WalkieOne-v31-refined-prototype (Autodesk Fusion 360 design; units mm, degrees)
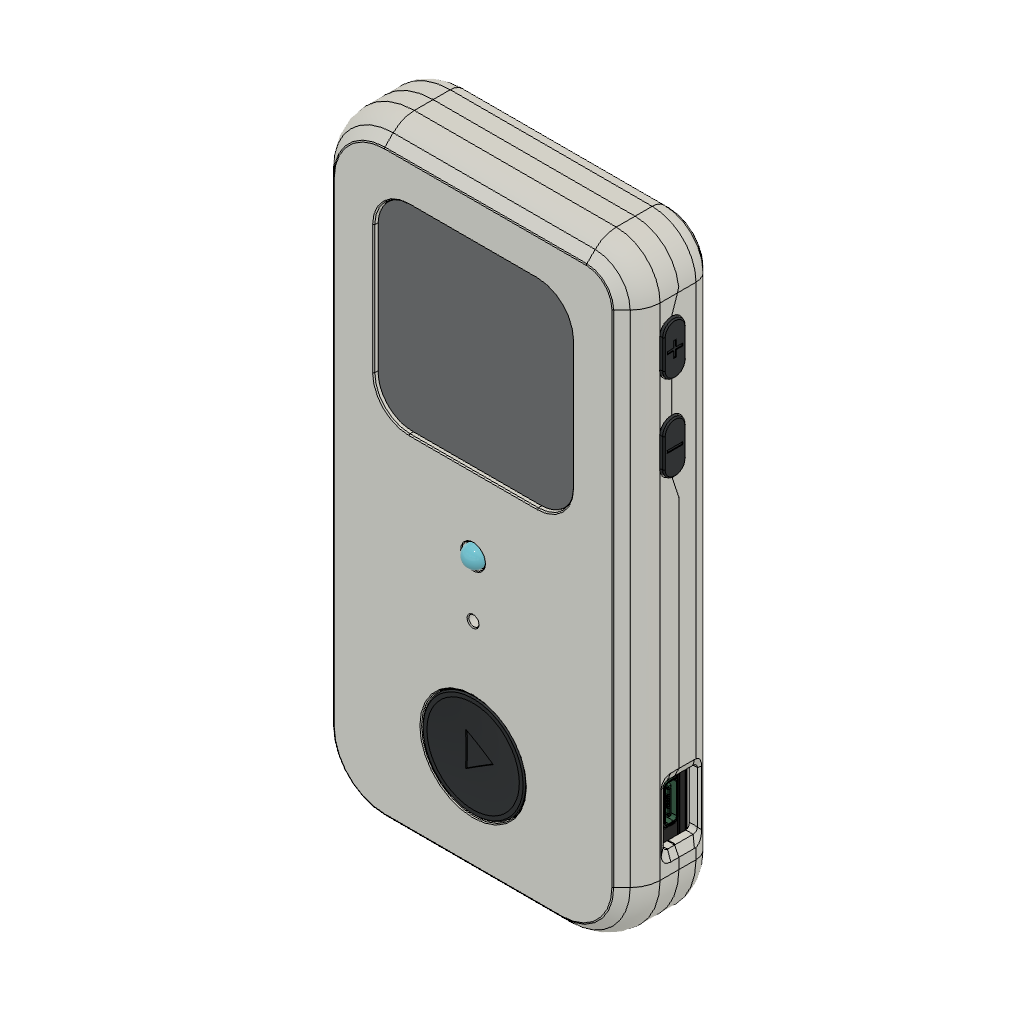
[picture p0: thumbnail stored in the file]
description: Part Number
part number: WO-V31-ASM
part number: WO-V31-M01
part number: WO-V31-M02
part number: WO-V31-M03
part number: WO-V31-M04
part number: WO-V31-M05
part number: WO-V31-M06
part number: WO-V31-M07
part number: WO-V31-M08
part number: WO-V31-M09
part number: WO-V31-M99
part number: WO-V31-BACK
part number: WO-V31-BATTERY_REFERENCE
part number: WO-V31-CASE_INSERTS_REFERENCE
part number: WO-V31-CASE_SCREWS_REFERENCE
parameter "REF_Body_Width" = 73.5 comment "Preserved v30 envelope; reference only, does not resize imported shells."
parameter "REF_Body_Height" = 143.25 comment "Preserved v30 envelope; reference only."
parameter "REF_Body_Thickness" = 19.4 comment "Preserved v30 envelope; excludes existing projections."
parameter "PTT_Link_Centres" = 8 comment "Link pivot centre spacing."
parameter "PTT_Link_Width" = 6.8 comment "Link capsule width."
parameter "PTT_Link_Bore" = 4.1 comment "Bearing bore; 0.1 mm diametral clearance over sleeve."
parameter "PTT_Link_Thickness" = 2.4 comment "Link thickness."
parameter "PTT_Sleeve_Flange_OD" = 6.6 comment "Sleeve flange diameter."
parameter "PTT_Sleeve_Bearing_OD" = 4 comment "Link bearing diameter."
parameter "PTT_Sleeve_Bore" = 2.3 comment "Screw clearance diameter."
parameter "PTT_Sleeve_Flange_T" = 1.2 comment "Sleeve flange thickness."
parameter "PTT_Sleeve_Bearing_L" = 2.55 comment "Bearing length; retains 0.15 mm total axial clearance."
parameter "Speaker_Spacer_OD" = 5 comment "Printed spacer diameter."
parameter "Speaker_Spacer_ID" = 2.2 comment "Speaker spacer clearance bore."
parameter "Speaker_Spacer_T" = 0.7 comment "Accepted v30 speaker stack thickness."
base_feature "Base Feature1" bodies "Rear shell"
base_feature "Base Feature1" bodies "Battery"
base_feature "Base Feature1" bodies "Case inserts 001", "Case inserts 002", "Case inserts 003", "Case inserts 004", "Battery"
base_feature "Base Feature1" bodies "Case screws 001", "Case screws 002", "Case screws 003", "Case screws 004", "Battery"
base_feature "Base Feature1" bodies "Front shell"
base_feature "Base Feature1" bodies "Grille adhesive - 0.26 mm"
base_feature "Base Feature1" bodies "Metal grille blank - 46 x 46 R8"
base_feature "Base Feature1" bodies "LED body"
base_feature "Base Feature1" bodies "LED formed leads 001", "LED formed leads 002", "LED formed leads 003", "LED formed leads 004"
base_feature "Base Feature1" bodies "LED inserts 001", "LED inserts 002"
base_feature "Base Feature1" bodies "LED insulated joint keepout 001", "LED insulated joint keepout 002", "LED insulated joint keepout 003", "LED insulated joint keepout 004", "Battery"
base_feature "Base Feature1" bodies "LED fork retainer"
base_feature "Base Feature1" bodies "LED screws 001", "LED screws 002"
base_feature "Base Feature1" bodies "LED soft pad"
base_feature "Base Feature1" bodies "Microphone gasket"
base_feature "Base Feature1" bodies "Microphone inserts 001", "Microphone inserts 002"
base_feature "Base Feature1" bodies "Microphone 001", "Microphone 002", "Microphone 003", "Microphone 004", "Microphone 005", "Microphone 006"
base_feature "Base Feature1" bodies "Microphone screws 001", "Microphone screws 002"
base_feature "Base Feature1" bodies "Microphone wire keepout"
base_feature "Base Feature1" bodies "PCB - exact fit reference 001", "PCB - exact fit reference 002", "PCB - exact fit reference 003", "PCB - exact fit reference 004", "PCB - exact fit reference 005", "PCB - exact fit reference 006", "PCB - exact fit reference 007", "PCB - exact fit reference 008"
base_feature "Base Feature1" bodies "PTT button cap"
base_feature "Base Feature1" bodies "PTT fixed screw 0"
base_feature "Base Feature1" bodies "PTT fixed screw 1"
base_feature "Base Feature1" bodies "PTT inserts 001", "PTT inserts 002", "PTT inserts 003", "PTT inserts 004", "PTT inserts 005", "PTT inserts 006"
base_feature "Base Feature1" bodies "PTT lower wire"
base_feature "Base Feature1" bodies "PTT mount screw 0"
base_feature "Base Feature1" bodies "PTT mount screw 1"
base_feature "Base Feature1" bodies "PTT moving screw 0"
base_feature "Base Feature1" bodies "PTT moving screw 1"
base_feature "Base Feature1" bodies "PTT switch"
base_feature "Base Feature1" bodies "PTT switch clamp"
base_feature "Base Feature1" bodies "PTT switch seat"
base_feature "Base Feature1" bodies "PTT upper wire"
base_feature "Base Feature1" bodies "Play button cap"
base_feature "Base Feature1" bodies "Play switch carrier"
base_feature "Base Feature1" bodies "Play foam 001", "Play foam 002", "Play foam 003", "Play foam 004", "Battery"
base_feature "Base Feature1" bodies "Play inserts 001", "Play inserts 002"
base_feature "Base Feature1" bodies "Play travel retainer - C 0.40"
base_feature "Base Feature1" bodies "Play screws 001", "Play screws 002"
base_feature "Base Feature1" bodies "Play switch"
base_feature "Base Feature1" bodies "Play wire keepout 001", "Play wire keepout 002", "Play wire keepout 003", "Play wire keepout 004", "Battery"
base_feature "Base Feature1" bodies "Speaker gasket"
base_feature "Base Feature1" bodies "Speaker inserts 001", "Speaker inserts 002"
base_feature "Base Feature1" bodies "Speaker 001", "Speaker 002", "Speaker 003", "Speaker 004", "Battery"
base_feature "Base Feature1" bodies "Speaker screws 001", "Speaker screws 002"
base_feature "Base Feature1" bodies "Speaker washers 001", "Speaker washers 002"
base_feature "Base Feature1" bodies "USB collar"
base_feature "Base Feature1" bodies "USB liner backers 001", "USB liner backers 002"
base_feature "Base Feature1" bodies "USB liner floor lift"
base_feature "Base Feature1" bodies "USB liner floor sides 001", "USB liner floor sides 002"
base_feature "Base Feature1" bodies "USB liner inner returns"
base_feature "Base Feature1" bodies "USB liner primary 001", "USB liner primary 002", "USB liner primary 003", "USB liner primary 004", "USB liner primary 005", "USB liner primary 006", "USB liner primary 007", "USB liner primary 008"
base_feature "Base Feature1" bodies "Volume body adhesive 001", "Volume body adhesive 002"
base_feature "Base Feature1" bodies "Volume minus cap"
base_feature "Base Feature1" bodies "Volume down switch"
base_feature "Base Feature1" bodies "Volume down wire A 001", "Volume down wire A 002", "Volume down wire A 003", "Volume down wire A 004", "Volume down wire A 005", "Volume down wire A 006", "Volume down wire A 007", "Volume down wire A 008"
base_feature "Base Feature1" bodies "Volume down wire B 001", "Volume down wire B 002", "Volume down wire B 003", "Volume down wire B 004", "Volume down wire B 005", "Volume down wire B 006", "Volume down wire B 007", "Volume down wire B 008"
base_feature "Base Feature1" bodies "Volume guide frame"
base_feature "Base Feature1" bodies "Volume insert 130"
base_feature "Base Feature1" bodies "Volume insert 93"
base_feature "Base Feature1" bodies "Volume switch keeper"
base_feature "Base Feature1" bodies "Volume screw 130"
base_feature "Base Feature1" bodies "Volume screw 93"
base_feature "Base Feature1" bodies "Volume plus cap"
base_feature "Base Feature1" bodies "Volume up switch"
base_feature "Base Feature1" bodies "Volume up wire A 001", "Volume up wire A 002", "Volume up wire A 003", "Volume up wire A 004", "Volume up wire A 005", "Volume up wire A 006", "Volume up wire A 007", "Volume up wire A 008"
base_feature "Base Feature1" bodies "Volume up wire B 001", "Volume up wire B 002", "Volume up wire B 003", "Volume up wire B 004", "Volume up wire B 005", "Volume up wire B 006", "Volume up wire B 007", "Volume up wire B 008"
place_component sketch "Link capsule and bearing bores"
sketch "Link capsule and bearing bores" plane through (0, 0, 0) normal (0, 0, 1) x axis (1, 0, 0)
  line L1 (8, -3.4) -> (0, -3.4)
  line L2 (0, 3.4) -> (8, 3.4)
  line L3 (8, 0) -> (0, 0)
  arc A1 centre (8, 0) radius 3.4 clockwise from (8, 3.4) to (8, -3.4)
  arc A2 centre (0, 0) radius 3.4 clockwise from (0, -3.4) to (0, 3.4)
  circle C1 centre (0, 0) radius 2.05
  circle C2 centre (8, 0) radius 2.05
  point P1 (0, 0)
  point P6 (0, 0)
  point P8 (0, 0)
  point P7 (8, 0)
  point P9 (8, 0)
  coincident P1 P6
  tangent L1 A1
  tangent A1 L2
  tangent L2 A2
  tangent L1 A2
  parallel L1 L2
  horizontal L3
  coincident P6 P8
  coincident P7 P9
  dimension "d16" diameter A1 = 6.8
  dimension "d17" distance P6 P7 = 8
  dimension "d18" diameter C1 = 4.1 (= "PTT_Link_Bore")
  dimension "d19" diameter C2 = 4.1 (= "PTT_Link_Bore")
extrude "Extrude1" new body sketch "Link capsule and bearing bores" profile of L1 A1 L2 A2 C1 C2 along normal blind 2.4 (= "PTT_Link_Thickness") bodies "PTT link - 8 mm centres"
copy_paste "CopyPaste1"
sketch "Flange and M2 clearance bore" plane through (0, 0, 0) normal (0, 0, 1) x axis (1, 0, 0)
  circle C1 centre (0, 0) radius 3.3
  circle C2 centre (0, 0) radius 1.15
  point P1 (0, 0)
  point P2 (0, 0)
  point P3 (0, 0)
  coincident P1 P2
  coincident P1 P3
  dimension "d22" diameter C1 = 6.6 (= "PTT_Sleeve_Flange_OD")
  dimension "d23" diameter C2 = 2.3 (= "PTT_Sleeve_Bore")
extrude "Extrude1" new body sketch "Flange and M2 clearance bore" along normal blind 1.2 (= "PTT_Sleeve_Flange_T") bodies "PTT shoulder sleeve - 4 places"
work_plane "WorkPlane1" AlongDistance 1.2 (= "PTT_Sleeve_Flange_T") ExtraOffset 0
sketch "Bearing diameter and clearance bore" plane through (0, 0, 1.2) normal (0, 0, 1) x axis (1, 0, 0)
  circle C1 centre (0, 0) radius 2
  circle C2 centre (0, 0) radius 1.15
  point P1 (0, 0)
  point P2 (0, 0)
  point P3 (0, 0)
  coincident P1 P2
  coincident P1 P3
  dimension "d28" diameter C1 = 4 (= "PTT_Sleeve_Bearing_OD")
  dimension "d29" diameter C2 = 2.3 (= "PTT_Sleeve_Bore")
extrude "Extrude2" add sketch "Bearing diameter and clearance bore" along normal blind 2.55 (= "PTT_Sleeve_Bearing_L")
copy_paste "CopyPaste2"
copy_paste "CopyPaste3"
copy_paste "CopyPaste4"
place_component sketch "Speaker spacer annulus"
sketch "Speaker spacer annulus" plane through (0, 0, 0) normal (0, 0, 1) x axis (1, 0, 0)
  circle C1 centre (0, 0) radius 2.5
  circle C2 centre (0, 0) radius 1.1
  point P1 (0, 0)
  point P2 (0, 0)
  point P3 (0, 0)
  coincident P1 P2
  coincident P1 P3
  dimension "d32" diameter C1 = 5 (= "Speaker_Spacer_OD")
  dimension "d33" diameter C2 = 2.2 (= "Speaker_Spacer_ID")
extrude "Extrude1" new body sketch "Speaker spacer annulus" along normal blind 0.7 (= "Speaker_Spacer_T") bodies "Speaker spacer - 0.7 mm - 2 places"
copy_paste "CopyPaste1"
position "Position1"
sketch "REFERENCE ONLY - preserved v30 73.5 x 143.25 envelope" plane through (0, 0, 0) normal (0, 0, 1) x axis (1, 0, 0)
  line L1 (72.75, -0.75) -> (-0.75, -0.75)
  line L2 (72.75, 142.5) -> (72.75, -0.75)
  line L3 (-0.75, 142.5) -> (72.75, 142.5)
  line L4 (-0.75, -0.75) -> (-0.75, 142.5)
position "Position2"
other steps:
create_component "CreateComponent1"
create_component "CreateComponent2"
create_component "CreateComponent3"
create_component "CreateComponent4"
create_component "CreateComponent5"
create_component "CreateComponent6"
create_component "CreateComponent7"
create_component "CreateComponent8"
create_component "CreateComponent9"
create_component "CreateComponent10"
create_component "CreateComponent1"
create_component "CreateComponent1"
create_component "CreateComponent1"
create_component "CreateComponent2"
create_component "CreateComponent2"
create_component "CreateComponent1"
create_component "CreateComponent2"
create_component "CreateComponent1"
create_component "CreateComponent1"
create_component "CreateComponent2"
create_component "CreateComponent2"
create_component "CreateComponent3"
create_component "CreateComponent4"
create_component "CreateComponent5"
create_component "CreateComponent2"
create_component "CreateComponent3"
create_component "CreateComponent4"
create_component "CreateComponent5"
create_component "CreateComponent3"
create_component "CreateComponent6"
create_component "CreateComponent1"
create_component "CreateComponent2"
create_component "CreateComponent3"
create_component "CreateComponent4"
create_component "CreateComponent4"
create_component "CreateComponent5"
create_component "CreateComponent6"
create_component "CreateComponent7"
create_component "CreateComponent8"
create_component "CreateComponent9"
create_component "CreateComponent10"
create_component "CreateComponent11"
create_component "CreateComponent5"
create_component "CreateComponent1"
create_component "CreateComponent2"
create_component "CreateComponent3"
create_component "CreateComponent4"
create_component "CreateComponent5"
create_component "CreateComponent6"
create_component "CreateComponent7"
create_component "CreateComponent6"
create_component "CreateComponent3"
create_component "CreateComponent4"
create_component "CreateComponent5"
create_component "CreateComponent6"
create_component "CreateComponent7"
create_component "CreateComponent1"
create_component "CreateComponent2"
create_component "CreateComponent3"
create_component "CreateComponent4"
create_component "CreateComponent5"
create_component "CreateComponent6"
create_component "CreateComponent1"
create_component "CreateComponent2"
create_component "CreateComponent3"
create_component "CreateComponent7"
create_component "CreateComponent8"
create_component "CreateComponent4"
create_component "CreateComponent5"
create_component "CreateComponent6"
create_component "CreateComponent7"
create_component "CreateComponent8"
create_component "CreateComponent9"
create_component "CreateComponent10"
create_component "CreateComponent11"
create_component "CreateComponent9"
create_component "CreateComponent10"
create_component "CreateComponent12" sketch "Link capsule and bearing bores"
create_component "CreateComponent13"
create_component "CreateComponent8" sketch "Speaker spacer annulus"
named bodies: "Rear shell", "Battery", "Case inserts 001", "Case inserts 002", "Case inserts 003", "Case inserts 004", "Case screws 001", "Case screws 002", "Case screws 003", "Case screws 004", "Front shell", "Grille adhesive - 0.26 mm", "Metal grille blank - 46 x 46 R8", "LED body", "LED formed leads 001", "LED formed leads 002", "LED formed leads 003", "LED formed leads 004", "LED inserts 001", "LED inserts 002", "LED insulated joint keepout 001", "LED insulated joint keepout 002", "LED insulated joint keepout 003", "LED insulated joint keepout 004", "LED fork retainer", "LED screws 001", "LED screws 002", "LED soft pad", "Microphone gasket", "Microphone inserts 001", "Microphone inserts 002", "Microphone 001", "Microphone 002", "Microphone 003", "Microphone 004", "Microphone 005", "Microphone 006", "Microphone screws 001", "Microphone screws 002", "Microphone wire keepout", "PCB - exact fit reference 001", "PCB - exact fit reference 002", "PCB - exact fit reference 003", "PCB - exact fit reference 004", "PCB - exact fit reference 005", "PCB - exact fit reference 006", "PCB - exact fit reference 007", "PCB - exact fit reference 008", "PCB - exact fit reference 009", "PCB - exact fit reference 010", "PCB - exact fit reference 011", "PCB - exact fit reference 012", "PCB - exact fit reference 013", "PCB - exact fit reference 014", "PCB - exact fit reference 015", "PCB - exact fit reference 016", "PCB - exact fit reference 017", "PCB - exact fit reference 018", "PCB - exact fit reference 019", "PCB - exact fit reference 020"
